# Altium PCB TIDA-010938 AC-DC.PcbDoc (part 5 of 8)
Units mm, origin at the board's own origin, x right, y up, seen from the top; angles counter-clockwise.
Board outline 280 x 180.15 mm, 4 copper layers (Top Layer, Layer 1, Layer 2, Bottom Layer), stack 1.787 mm thick; 723 components, 427 nets, 2244 pads, 2295 vias.
Unrouted connection lines stored in the file: 17.
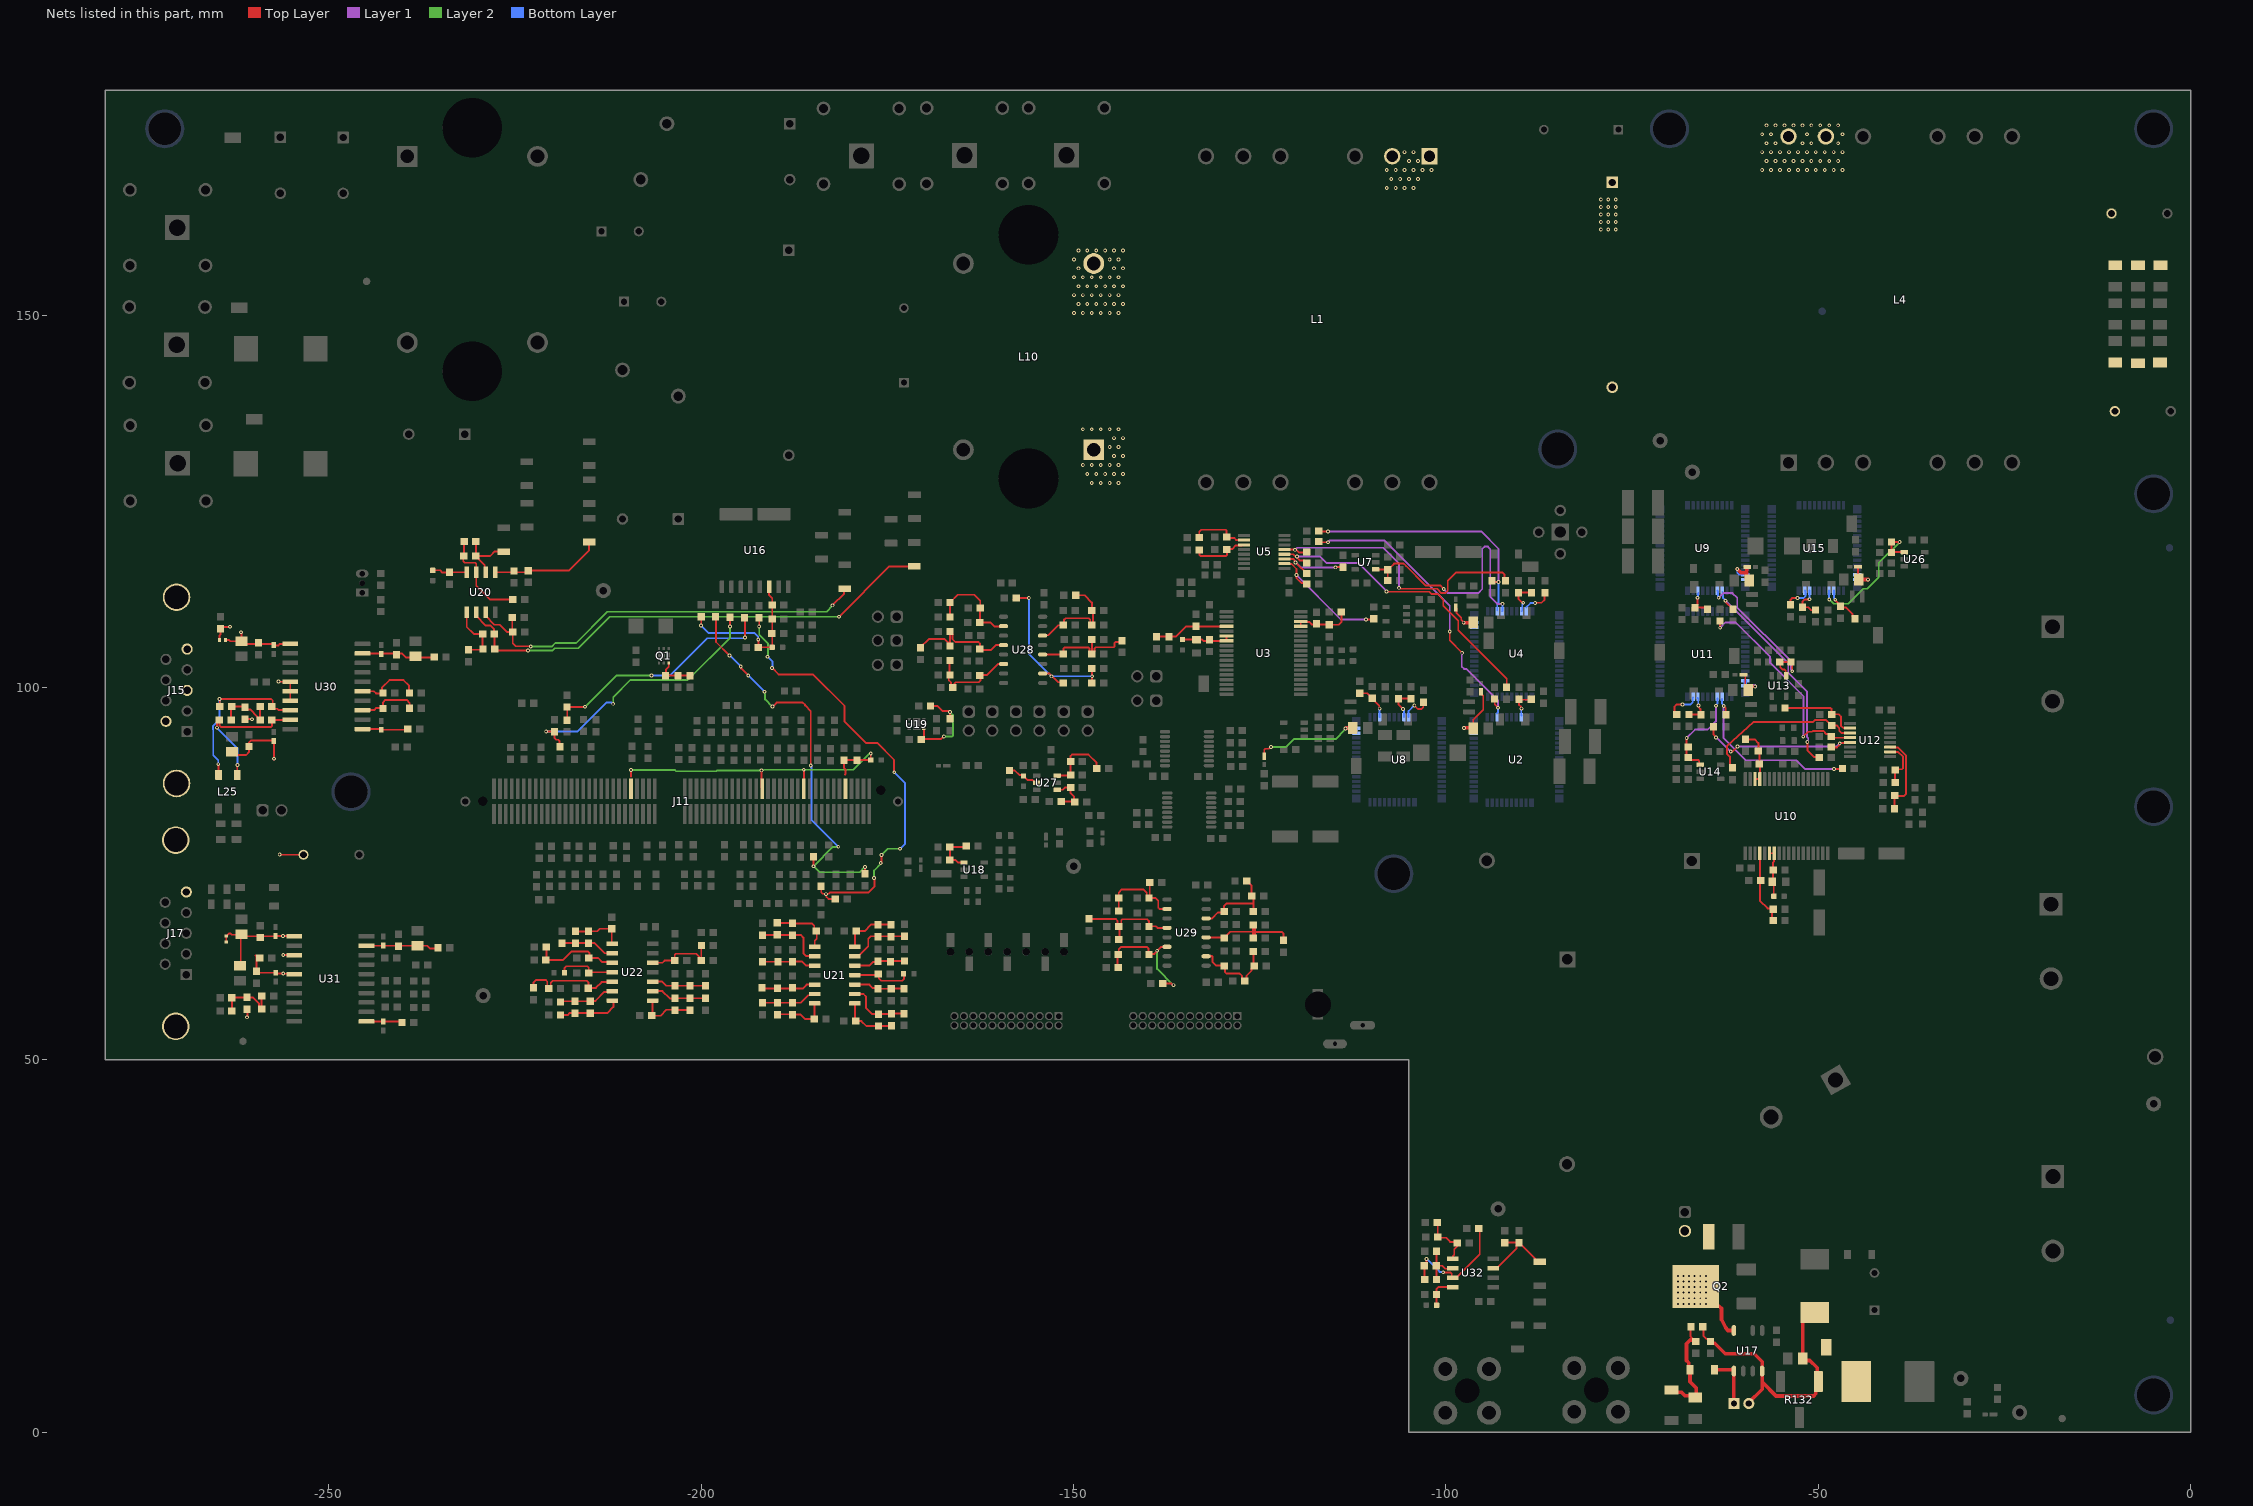
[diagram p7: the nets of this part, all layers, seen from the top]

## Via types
v1: diameter 0.508, hole 0.254, Top Layer to Bottom Layer, tented both sides, 2041 vias
v2: diameter 0.508, hole 0.254, Top Layer to Bottom Layer, 252 vias
v3: diameter 0.5, hole 0.2, Top Layer to Bottom Layer, 2 vias

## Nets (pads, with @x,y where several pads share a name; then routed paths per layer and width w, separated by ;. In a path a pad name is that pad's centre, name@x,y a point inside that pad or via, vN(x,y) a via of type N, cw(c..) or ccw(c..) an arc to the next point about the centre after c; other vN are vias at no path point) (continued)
F\A\U\L\T\_S3: C249.2 R331.2 U9.46 U13.1 | length 22
  Top Layer w0.25: C249.2@-55.19,103.421 R331.2@-53.69,103.421 -53.515,103.246 v1(-53.515,102.171) ; C249.2@-55.19,103.449 -55.121,103.38 -55.121,102.692 -54.85,102.421 -54.59,102.421 -54.39,102.221 -54.39,101.821 U13.1@-54.462,101.893
  Layer 1 w0.25: v1(-63.39,112.046) -62.765,112.671 -61.54,112.671 -60.89,112.021 -60.89,110.721 -53.658,103.489 -53.658,102.411 -53.499,102.251 v1@-53.421,102.251
  Bottom Layer w0.25: U9.46@-63.575,112.996 -63.475,112.896 -63.475,112.175 -63.39,112.09 v1@-63.39,112.021
F\A\U\L\T\_S4_init: C254.2 R336.2 U15.46 U26.1 | length 19.6
  Top Layer w0.25: C254.2@-40.19,118.121 -40.14,118.171 U26.1@-38.465,118.171 -38.34,118.171 U26.1@-38.315,118.196 ; C254.2@-40.14,118.371 -40.19,118.421 R336.2@-40.19,119.521 -39.313,119.521 -39.163,119.371 v1@-39.115,119.371
  Layer 2 w0.25: v1(-48.54,111.821) -47.961,111.242 -46.008,111.242 -44,113.25 -43.45,113.25 -41.9,114.8 -41.9,116.711 v1(-39.09,119.521)
  Bottom Layer w0.25: U15.46@-48.575,112.996 -48.558,112.978 -48.558,111.838 v1(-48.54,111.821)
F\A\U\L\T\_S5: C247.2 R329.2 U4.46 U7.1 | length 34.1
  Top Layer w0.25: U7.1@-109.45,115.85 -108.025,115.85 C247.2@-107.947,115.928 ; R329.2@-107.825,114.325 R329.2@-107.8,114.35 ; R329.2@-107.775,114.5 -107.817,114.542 C247.2@-107.817,115.798 -107.825,115.807 -107.825,115.928 -107.662,115.928 -106.965,116.625 -105.679,116.625 -105.358,116.303 -102.754,113.7 -100.8,113.7 v1(-100.3,113.2)
  Layer 1 w0.25: v1(-100.3,113.2) -99.775,112.675 -95.671,112.675 -95.127,113.219 -95.127,116.239 -95.131,116.243 -95.131,118.599 -94.821,118.909 -94.383,118.909 -94.055,118.581 -94.055,112.178 -93.102,111.225 v1(-92.4,111.225)
  Bottom Layer w0.25: U4.46@-92.465,110.225 -92.433,110.258 -92.433,111.217 v1@-92.4,111.25
F\A\U\L\T\_S6: C48.2 R33.2 U11.46 U14.1 | length 12.9
  Top Layer w0.25: C48.2@-67.69,90.621 -67.34,90.271 -66.14,90.271 -65.99,90.121 U14.1@-65.99,89.621 ; C48.2@-67.69,90.721 -67.69,91.821 v1(-67.69,93.221)
  Layer 1 w0.25: v1(-67.69,93.221) -66.553,94.358 -64.853,94.358 -63.765,95.446 v1(-63.765,97.546) v1@-63.765,97.571
  Bottom Layer w0.25: v1(-63.765,97.546) -63.765,97.615 -63.565,97.815 U11.46@-63.565,98.521
GND_ISO_COMM: C1.1 C198.1 C205.2 C207.2 C211.1 C220.1 C223.1 C224.2 C225.2 C226.1 C227.2 C228.2 C236.1 FB18.2 FB23.1 FB23.2 J15.3 J15.5 J15.6 J15.10 J15.11 J17.5 J17.10 J17.11 R126.1 U30.15 U30.16 U30.17 U31.11 U31.13 U31.15 | length 44.1
  Top Layer w0.25: FB18.2@-264.652,106.371 -264.652,106.973 -264.506,107.119 C211.1@-264.506,107.885 -264.506,108.058 -264.439,108.125 v1@-263.2,108.125 ; FB23.1@-263.75,65.85 FB23.2@-263.75,66.65 -263.7,66.65 -263.37,66.98 -263.18,66.98 -263,66.8 C228.2@-261.8,66.8 ; C207.2@-262.982,91.618 -262.982,91.601 -262.313,90.932 -261.083,90.932 -260.696,91.319 -260.696,92.073 -260.696,92.596 -260.394,92.898 -257.496,92.898 -257.359,92.761 -257.359,90.441 -257.4,90.4 v1@-257.352,90.352 ; C225.2@-261.9,62.632 -261.795,62.737 C228.2@-261.795,66.705 ; C228.2@-261.719,66.861 -261.465,66.607 C227.2@-257.311,66.607 ; C220.1@-261.247,95.749 -260.274,95.749 v1@-260.25,95.725 ; C236.1@-260.946,56.782 -260.9,56.736 v1@-260.9,55.7 ; -259.8,64 -259.7,63.9 C223.1@-259.7,61.9 C223.1@-259.7,61.727 ; C223.1@-259.3,61.7 C224.2@-257.1,61.7 -257,61.6 v1(-256.1,61.6) -256.059,61.559 -255.159,61.559 U31.15@-255.1,61.5 ; C227.2@-257.136,66.634 v1(-256.138,66.634) -255.141,66.634 U31.11@-255.075,66.7 ; v1@-256.775,100.75 -256.593,100.75 -256.581,100.762 U30.15@-255.156,100.762 U30.16@-255.156,99.492 -255.156,98.356 U30.17@-255.15,98.35 ; v1@-256.5,77.525 -256.485,77.54 C1.1@-253.416,77.54 ; v1(-256.1,64.1) -256.08,64.079 -254.64,64.079 U31.13@-254.62,64.059
  other v1: -260.974,55.717 -256.575,77.575 -257.323,90.428 -260.275,95.725 -256.725,100.8 -263.225,108.15
IAC_F\A\U\L\T\: C113.2 R88.2 R229.1 | length 54.6
  Top Layer w0.25: R88.2@-198,109.3 -198,106.1 v1(-196.2,104.3) ; v1@-194.7,102.9 -194.625,102.825 -194.625,102.567 v1(-193.674,101.617) ; v1(-190.4,97.43) -189.871,97.959 -186.356,97.959 -186.046,97.649 -186.046,97.594 -185.274,96.822 v1(-185.274,89.517) ; v1@-184.9,76.1 -184.9,77.243 R229.1@-184.892,77.251 ; v1(-178,75.9) -178,75.3 C113.2@-177.8,75.1
  Layer 2 w0.25: v1@-191.425,99.418 -191.425,99.185 -191.4,99.16 -191.4,98.4 -190.43,97.43 v1(-190.4,97.43) ; v1@-181.5,78.6 -182.3,78.6 v1(-184.9,76) -184.1,75.2 -178.7,75.2 v1(-178,75.9)
  Bottom Layer w0.25: v1(-196.2,104.3) -196.179,104.3 -194.769,102.89 -194.697,102.89 v1@-194.687,102.9 ; v1@-193.6,101.6 -193.6,101.543 v1(-191.474,99.417) ; v1@-185.2,89.5 -185.2,82.243 v1(-181.574,78.617)
  other v1: -194.674,102.817
IAC_O\C\: C108.2 R87.2 R231.1 | length 60.7
  Top Layer w0.25: v1(-192.2,108.189) R87.2@-192.2,109.2 ; v1(-190.474,102.617) -189.607,101.75 -184.984,101.75 -180.745,97.511 -180.745,95.397 -177.894,92.546 -176.351,92.546 -174.1,90.295 v1@-174.1,88.6 ; R231.1@-184.085,73.5 R231.1@-183.876,73.291 -183.876,72.476 -183.699,72.299 -183.299,72.299 v1(-183.25,72.25) ; C108.2@-182.1,71.6 -182.875,71.6 -183.201,71.926 -183.201,72.131 -183.25,72.18 v1(-183.25,72.25) ; v1@-176.7,74.545 -176.7,73.336 -177.586,72.45 -182.724,72.45 -182.875,72.299 -183.201,72.299 v1(-183.25,72.25) ; v1@-175.8,76.6 -175.774,76.626 v1(-175.774,77.517)
  Layer 2 w0.25: v1(-192.2,108.189) -192.2,107.048 -191,105.848 v1@-191,104.1 ; v1(-176.774,74.417) -176.774,75.426 v1@-175.8,76.4 ; v1@-175.8,77.5 -174.957,78.343 v1(-173.303,78.343)
  Bottom Layer w0.25: v1(-191.074,104.117) -190.4,103.443 v1@-190.4,102.6 ; v1(-174.074,88.617) -172.608,87.151 -172.608,78.992 v1@-173.2,78.4
  other v1: -175.874,76.417
IAC_REF: C112.2 R86.1 R181.1 | length 36.6
  Top Layer w0.25: v1(-220.8,94.1) -219.726,94.1 C112.2@-219.698,94.072 -219.698,93.223 -219.45,92.975 -219.171,92.975 -219.025,92.829 -219.025,92.4 -218.875,92.25 R181.1@-218.825,92.25 ; v1(-196.1,108.189) R86.1@-196.1,109.2
  Layer 2 w0.25: v1(-211.8,97.8) -211.8,98.698 -209.498,101 -201.802,101 -196.1,106.702 v1(-196.1,108.189)
  Bottom Layer w0.25: v1(-220.8,94.1) -216.565,94.1 -212.665,98 -212.07,98 -211.87,97.8 v1(-211.8,97.8)
IAC_sense: C107.2 R83.2 R180.1 | length 32
  Top Layer w0.25: R180.1@-218.1,95.7 -217.975,95.825 C107.2@-217.975,97.375 -217.95,97.4 v1@-215.5,97.4 ; v1(-194.1,106.7) R83.2@-194.1,109.2
  Layer 2 w0.25: v1(-215.574,97.417) -211.391,101.6 v1@-206.6,101.6
  Bottom Layer w0.25: v1(-206.674,101.617) -204.133,101.617 -199.15,106.6 v1@-194.2,106.6
IN_PWM_S1: C13.2 R9.2 U2.45 | length 40.1
  Top Layer w0.25: R9.2@-117.075,119.6 -116.975,119.5 -115.95,119.5 v1@-115.875,119.575 ; v1(-99.5,107.525) -99.5,106.325 v1@-97.85,104.675 ; C13.2@-93.475,98.403 -93.446,98.375 -93.446,97.721 v1(-93,97.275)
  Layer 1 w0.25: v1(-115.85,119.5) -115.825,119.5 -115.575,119.75 -108.275,119.75 -99.5,110.975 v1(-99.5,107.525) ; v1@-97.781,104.575 -97.83,104.575 -97.874,104.531 -97.874,104.418 -97.879,104.414 -97.879,102.806 -97.569,102.496 -97.287,102.496 -93,98.209 v1(-93,97.275)
  Bottom Layer w0.25: U2.45@-93.175,96.5 -93.029,96.646 -93.029,97.246 v1(-93,97.275)
  other v1: -97.825,104.65
IN_PWM_S3: C59.2 R19.2 U9.45 | length 29.6
  Top Layer w0.25: v1(-62.463,111.642) -62.414,111.592 -62.414,111.469 -61.49,110.546 C59.2@-61.49,110.521 ; v1(-51.49,92.696) -51.49,91.546 -50.619,90.674 -49.969,90.674 R19.2@-49.89,90.596
  Layer 1 w0.25: v1(-62.463,111.642) -54.058,103.237 -54.058,101.966 -51.519,99.426 -51.519,93.961 -51.511,93.953 -51.511,93.318 -51.371,93.178 -51.371,92.885 -51.49,92.765 v1(-51.49,92.696)
  Bottom Layer w0.25: U9.45@-62.89,112.821 -62.825,112.756 -62.825,112.073 -62.463,111.711 v1(-62.463,111.642)
IN_PWM_S5: C26.1 R8.2 U4.45 | length 34.3
  Top Layer w0.25: R8.2@-117.075,121 -117.025,120.95 v1@-115.95,120.95 ; C26.1@-93.8,114.3 -93.648,114.148 v1(-92.96,114.148)
  Layer 1 w0.25: v1(-115.85,120.95) -95.292,120.95 -92.95,118.608 -92.95,114.158 v1(-92.96,114.148)
  Bottom Layer w0.25: U4.45@-93.115,110.325 -93.115,111.26 -92.96,111.415 v1(-92.96,114.148)
IN_PWM_S6: C71.2 R18.2 U11.45 | length 24.1
  Top Layer w0.25: v1(-62.715,97.521) -62.715,97.471 -62.44,97.196 -62.44,96.421 C71.2@-62.39,96.371 ; v1(-47.915,89.071) -47.09,89.071 R18.2@-47.065,89.046
  Layer 1 w0.25: v1@-62.715,97.496 -62.765,97.446 -62.765,93.222 -59.763,90.221 -52.963,90.221 -51.813,89.071 v1(-47.915,89.071)
  Bottom Layer w0.25: U11.45@-62.94,98.471 -62.94,97.815 -62.715,97.59 v1(-62.715,97.521)
NetC6_1: C6.1 R23.1 R113.2 U20.3 | length 56.7
  Top Layer w0.25: U20.3@-228.915,110.075 -228.915,109.6 -227.74,108.425 -227.032,108.425 -226.031,107.424 -225.434,107.424 R23.1@-225.358,107.5 ; C6.1@-225.358,109.366 R23.1@-225.358,107.5 ; v1(-222.871,105.49) -222.92,105.539 -224.89,105.539 -225.281,105.931 R23.1@-225.281,107.424 R23.1@-225.358,107.5 ; v1(-182.368,111.023) -180.811,112.58 -180.811,113.166 R113.2@-180.717,113.259
  Layer 2 w0.25: v1(-222.871,105.49) -220.03,105.49 -219.551,105.97 -216.78,105.97 -212.585,110.165 -183.15,110.165 v1@-182.368,110.947
NetC7_2: C7.2 R2.1 R3.2 U21.3 | length 6.8
  Top Layer w0.25: U21.3@-179.347,60.117 -177.396,60.117 -176.929,59.65 -176.3,59.65 -176.2,59.55 R2.1@-174.475,59.55 ; R2.1@-174.475,59.575 -172.8,59.575 R3.2@-172.775,59.55
NetC8_1: C8.1 R4.2 R97.2 U21.2 | length 8.6
  Top Layer w0.25: U21.2@-179.347,58.847 -178.198,58.847 -177.885,58.534 -177.885,57.031 -177.004,56.15 C8.1@-176.2,56.15 -176.175,56.175 R97.2@-174.45,56.175 -174.4,56.225 R4.2@-172.75,56.225
NetC8_2: C8.2 R97.1 R140.1 U21.1 | length 7.8
  Top Layer w0.25: U21.1@-179.347,57.577 -179.347,55.57 -179.137,55.279 R140.1@-179.008,55.101 ; R140.1@-179.219,55.22 -179.008,55.22 -178.469,55.22 -177.799,54.55 C8.2@-176.2,54.55 ; C8.2@-176.25,54.325 -176.225,54.325 C8.2@-176.075,54.175 ; C8.2@-176.175,54.575 R97.1@-174.45,54.575
NetC9_2: C9.2 R119.1 R137.2 U21.5 | length 6.9
  Top Layer w0.25: U21.5@-179.347,62.657 -177.42,62.657 -176.916,63.161 -176.289,63.161 C9.2@-176.225,63.225 -176.175,63.275 R137.2@-172.7,63.275
NetC14_2: C14.2 R10.2 U2.50 | length 3.8
  Top Layer w0.25: v1@-89.9,97.275 -89.9,97.4 -90.2,97.7 R10.2@-90.2,98.425 -90.125,98.35 C14.2@-88.675,98.35
  Bottom Layer w0.25: v1(-89.875,97.15) -89.888,97.137 -89.888,96.288 U2.50@-89.85,96.25
NetC15_1: C15.1 D4.1 U2.40 U2.41 | length 8.6
  Top Layer w0.25: C15.1@-96.341,94.5 -96.341,95.659 -95,97 -95,98.884 -95.146,99.03 -95.175,99.03 -95.3,99.155 D4.1@-95.3,99.43
  Top Layer w0.5: v1(-97.575,94.575) -96.675,94.575 C15.1@-96.6,94.5
  Bottom Layer w0.25: v1(-97.575,94.575) -97.537,94.537 -96.298,94.537 U2.41@-96.26,94.5 U2.40@-96.26,93.85
NetC18_2: C18.2 C22.1 FB2.2 U3.6 U3.7 | length 6.7
  Top Layer w0.25: FB2.2@-135.475,106.425 FB2.2@-135.375,106.425 C18.2@-133.475,106.425 -132.737,106.425 -132.562,106.25 U3.7@-129.45,106.25 ; U3.7@-129.45,106.325 U3.6@-129.45,106.9
NetC21_1: C21.1 R12.2 R15.1 U3.33 U3.34 | length 7.6
  Top Layer w0.25: U3.33@-119.5,108.25 U3.34@-119.5,108.85 -119.45,108.8 -118.375,108.8 -118.05,108.475 R12.2@-115.675,108.475 ; R12.2@-115.675,108.425 -114.4,108.425 -114.05,108.775 R15.1@-114.05,109.975
NetC23_2: C23.2 R13.2 R14.2 U3.4 | length 10
  Top Layer w0.25: R14.2@-138.875,106.825 R13.2@-137.2,106.825 ; R13.2@-137.175,106.825 -136.25,106.825 -134.875,108.2 C23.2@-133.55,108.2 -131.9,108.2 ; -131.975,108.2 U3.4@-129.45,108.2
NetC25_2: C25.2 U4.51 | length 3.7
  Top Layer w0.25: v1@-87.9,111.375 -87.175,111.375 -86.75,111.8 -86.75,112.675 C25.2@-86.7,112.725
  Bottom Layer w0.25: U4.51@-89.225,110.75 -88.654,111.321 -88.054,111.321 v1(-88.025,111.35)
NetC27_2: C27.2 R30.2 U4.50 | length 4.5
  Top Layer w0.25: v1@-89.7,111.3 -90.25,111.85 R30.2@-90.25,112.725 -88.65,112.725 C27.2@-88.6,112.675
  Bottom Layer w0.25: U4.50@-89.865,110.225 -89.765,110.325 -89.765,111.165 -89.655,111.275 v1@-89.6,111.275
  other v1: -89.625,111.375
NetC28_1: C28.1 D10.1 U4.40 U4.41 | length 6
  Top Layer w0.25: D10.1@-98.7,110.73 -98.6,110.63 -98.6,110 -97.95,109.35 -97.95,109.095 -97.625,108.77 v1(-97.625,108.7) ; C28.1@-96.2,108.5 C28.1@-96.07,108.37
  Top Layer w0.5: v1(-97.625,108.7) C28.1@-96.316,108.7
  Bottom Layer w0.25: v1(-97.625,108.7) -97.612,108.713 -96.238,108.713 U4.41@-96.225,108.7
  Bottom Layer w0.5: U4.40@-96.225,108.075 U4.41@-96.225,108.7
NetC29_2: C29.2 R16.2 R105.2 U19.4 | length 13.3
  Top Layer w0.25: U19.4@-170.085,94.426 -170.085,93.35 -170.185,93.25 -170.2,93.25 C29.2@-170.45,93 -170.386,93.064 -167.82,93.064 -167.483,93.401 v1(-167.413,93.401) ; R16.2@-169.2,97.5 -168.25,97.5 -167.575,96.825 -166.595,96.825 -166.595,95.805 R105.2@-166.6,95.8
  Layer 2 w0.25: v1(-167.413,93.401) -166.314,93.401 -166.168,93.548 -166.168,96.245 -166.595,96.672 v1(-166.595,96.708)
NetC32_2: C32.2 R32.1 U5.2 | length 17.5
  Top Layer w0.25: U5.2@-121.675,116.613 -121.635,116.572 -120.734,116.572 -120.066,115.905 -120.066,115.1 -120.066,114.691 -119.404,114.029 -118.979,114.029 C32.2@-118.85,113.9 ; v1(-110.75,109.125) -109.7,109.125 R32.1@-109.65,109.075
  Layer 1 w0.25: v1(-120.075,115.1) -114.1,109.125 -110.825,109.125 v1@-110.8,109.1
NetC33_2: C33.2 R29.1 U5.3 | length 10.5
  Top Layer w0.25: U5.3@-121.675,117.248 -120.525,117.248 -120.238,116.961 -120.238,116.84 v1(-120.189,116.791) ; v1@-120.15,116.791 -120.15,116.75 C33.2@-118.65,115.25 ; v1@-114.75,116.05 -114.65,116.15 R29.1@-113.8,116.15
  Layer 1 w0.25: v1(-120.189,116.791) -120.135,116.791 -119.469,116.125 v1(-114.85,116.125)
NetC34_2: C34.2 R27.1 U5.4 | length 40.9
  Top Layer w0.25: U5.4@-121.675,117.883 -120.479,117.883 v1@-120.079,117.483 ; v1(-119.982,117.568) -119.994,117.568 v1@-120.079,117.483 ; C34.2@-118.9,116.625 -118.9,116.9 -119.05,117.05 -119.646,117.05 v1@-120.079,117.483 ; v1(-107.975,112.875) -107.946,112.846 -102.246,112.846 -101.95,112.55 -101.127,112.55 -100.371,111.794 -100.371,110.971 -98.35,108.95 -98.35,107.675 -91.85,101.175 R27.1@-91.85,100.025
  Layer 1 w0.25: v1(-119.982,117.568) -116.891,117.568 -116.044,116.721 -115.606,116.721 -115.602,116.725 -111.775,116.725 -107.975,112.925 v1(-107.975,112.875)
NetC35_2: C35.2 R25.1 U5.5 | length 38.8
  Top Layer w0.25: U5.5@-121.675,118.518 -120.093,118.518 -119.675,118.1 -118.85,118.1 C35.2@-118.825,118.075 ; v1(-106.3,113.375) -106.23,113.375 -106.101,113.246 -101.18,113.246 -100.605,112.671 -100.081,112.671 -99.771,112.981 -99.771,114.329 -98.65,115.45 -92.425,115.45 -92.125,115.15 -92.125,114.275 R25.1@-91.975,114.125
  Layer 1 w0.25: v1(-120.25,118.475) -119.975,118.75 -108.45,118.75 -106.3,116.6 v1(-106.3,113.375)
NetC41_2: C41.2 R22.2 U5.11 | length 7.3
  Top Layer w0.25: R22.2@-133.1,118.2 -133.1,117.8 -132.925,117.625 -129.546,117.625 -129.4,117.771 -129.4,118.525 -129.352,118.574 -128.721,118.574 -128.22,119.075 U5.11@-127.35,119.075
NetC42_2: C42.2 R20.2 U5.10 | length 7.4
  Top Layer w0.25: R20.2@-133.125,120.45 -133.125,120.875 -132.825,121.175 -129.596,121.175 -129.45,121.029 C42.2@-129.45,120.225 ; C42.2@-129.35,120.075 -128.45,120.075 -128.191,119.816 -127.154,119.816 U5.10@-127.125,119.788
NetC45_1: C45.1 R36.1 R118.2 U20.5 | length 14.9
  Top Layer w0.25: U20.5@-227.638,115.468 U20.5@-227.645,115.475 -223.422,115.475 R36.1@-223.2,115.697 -217.776,115.697 -215.033,118.44 R118.2@-215.033,119.532
NetC50_2: C50.2 U8.51 | length 4.1
  Top Layer w0.25: v1(-104.25,97.596) -103.754,97.1 -103.3,97.1 -103.05,97.35 -103.05,98.025 C50.2@-103.075,98.05
  Bottom Layer w0.25: U8.51@-105.008,96.025 -105.008,96.838 v1(-104.25,97.596)
NetC51_2: C51.2 R35.2 U8.45 | length 5
  Top Layer w0.25: R35.2@-111.525,99.175 R35.2@-111.575,99.225 -110.575,99.225 -109.9,98.55 C51.2@-109.9,98.525 -109.9,98.5 -108.949,97.549 -108.949,97.199 v1(-108.9,97.15)
  Bottom Layer w0.25: U8.45@-108.908,96.025 -108.904,96.029 -108.904,97.146 v1(-108.9,97.15)
NetC53_2: C53.2 R40.2 U8.50 | length 4.4
  Top Layer w0.25: v1@-105.8,97.125 -106.35,97.675 -106.35,98.45 R40.2@-106.4,98.5 C53.2@-104.7,98.5
  Bottom Layer w0.25: v1(-105.775,97.1) -105.775,97.03 -105.658,96.913 U8.50@-105.658,96.025
NetC54_1: C54.1 D25.1 U8.40 U8.41 | length 16.3
  Top Layer w0.25: D25.1@-124.4,90.77 -124.4,91.646 -124.275,91.771 -123.799,91.771 -123.57,92 v1(-123.5,92)
  Top Layer w0.5: v1@-113.425,94.525 -113.4,94.55 C54.1@-112.541,94.55 C54.1@-112.241,94.55
  Layer 2 w0.25: v1(-123.5,92) -121.5,92 -120.429,93.071 -114.829,93.071 -113.604,94.296 -113.604,94.301 -113.443,94.463 -113.437,94.463 v1@-113.437,94.468
  Bottom Layer w0.25: v1(-113.475,94.5) -113.463,94.513 -112.031,94.513 -112.018,94.5 U8.40@-112.018,93.875
NetC55_2: C55.2 FB11.2 U27.5 | length 4.3
  Top Layer w0.25: C55.2@-158.6,88.85 -157.883,88.85 -157.293,88.259 -156.859,88.259 -156.2,87.6 -155.525,87.6 -155.15,87.225 U27.5@-154.95,87.225
NetC56_2: C56.2 R68.1 R110.2 U32.3 | length 10.9
  Top Layer w0.25: U32.3@-93.675,22.035 -93.2,22.035 -90.521,24.714 -90.521,25.131 R68.1@-90.181,25.471 ; C56.2@-92.114,25.471 R68.1@-90.181,25.471 ; R68.1@-90.171,25.456 -87.9,23.186 R110.2@-87.9,22.576 ; R68.1@-90.171,25.481 R68.1@-90.181,25.471
NetC60_2: C60.2 R44.2 U9.50 | length 4.3
  Top Layer w0.25: C60.2@-66.69,110.921 -66.415,110.921 -66.24,111.096 v1@-66.24,111.921 ; v1@-66.315,111.971 v1@-66.253,111.908 ; C60.2@-66.29,110.421 C60.2@-66.59,110.721 -65.19,110.721 R44.2@-64.99,110.521
  Bottom Layer w0.25: v1@-66.16,112.021 -66.168,112.028 -66.168,112.643 U9.50@-66.09,112.721
  other v1: -66.24,112.046
NetC61_1: C61.1 D26.1 U9.40 U9.41 | length 5.9
  Top Layer w0.5: v1(-60.9,115.9) -60.898,115.9 -60.544,115.546 -60.531,115.546 -60.385,115.4 -59.668,115.4 -59.668,114.714 C61.1@-59.299,114.346 ; C61.1@-59.63,114.841 -59.63,115.4 -59.63,116.121 D26.1@-59.59,116.121
  Bottom Layer w0.25: v1(-60.9,115.9) -60.898,115.898 -60.898,115.398 -60.671,115.171 U9.40@-60.171,115.171 ; U9.40@-59.815,115.146 -59.79,115.146 -59.765,115.121 -59.765,114.98 U9.41@-59.765,114.596
NetC64_2: C64.2 C67.1 FB4.2 U10.6 U10.7 | length 6.6
  Top Layer w0.25: U10.6@-56.565,77.746 -56.015,77.746 U10.7@-55.965,77.696 ; C64.2@-56.215,73.921 -56.153,73.858 -55.99,73.696 FB4.2@-55.99,71.971 ; C64.2@-56.09,73.921 -56.09,76.496 -55.965,76.621 U10.7@-55.965,77.696 ; U10.7@-55.915,77.746 U10.7@-55.965,77.696
NetC66_1: C66.1 R45.2 R49.1 U10.33 U10.34 | length 7.2
  Top Layer w0.25: R49.1@-59.79,93.021 -58.565,93.021 -58.065,92.521 R45.2@-58.065,91.621 ; U10.34@-58.515,87.696 U10.33@-57.965,87.696 ; R45.2@-58.09,91.396 -57.915,91.221 C66.1@-57.915,89.721 ; U10.33@-57.865,87.696 C66.1@-57.865,89.721
NetC68_2: C68.2 R46.2 R48.2 U10.4 | length 10.1
  Top Layer w0.25: U10.4@-57.865,77.746 -57.865,74.071 -57.865,71.396 -56.819,70.349 -56.345,70.349 R46.2@-56.215,70.22 ; R48.2@-56.215,68.671 -56.215,70.096 R46.2@-56.115,70.196
NetC70_2: C70.2 U11.51 | length 4.4
  Top Layer w0.25: C70.2@-69.315,96.371 -69.315,97.446 -69.04,97.721 -68.34,97.721 v1@-68.29,97.771
  Bottom Layer w0.25: v1(-68.265,97.721) -67.165,97.721 -66.865,98.021 -66.865,98.621 U11.51@-66.84,98.646
NetC72_2: C72.2 R60.2 U11.50 | length 4.1
  Top Layer w0.25: C72.2@-67.565,96.371 R60.2@-65.84,96.371 ; v1(-66.09,97.596) -66.065,97.571 -66.065,97.321 -65.84,97.096 R60.2@-65.84,96.396
  Bottom Layer w0.25: U11.50@-66.215,98.596 -66.133,98.513 -66.133,97.638 v1(-66.09,97.596)
NetC73_1: C73.1 D27.1 U11.40 U11.41 | length 4.1
  Top Layer w0.25: D27.1@-59.82,101.721 -59.82,100.451 C73.1@-59.79,100.421
  Top Layer w0.5: C73.1@-59.649,100.146 v1(-58.49,100.146)
  Bottom Layer w0.5: U11.41@-59.815,100.321 U11.40@-59.815,100.896 ; U11.41@-59.49,100.221 -58.567,100.221 -58.492,100.146 v1(-58.49,100.146)
NetC74_1: C74.1 R129.2 R130.2 U20.6 | length 8.7
  Top Layer w0.25: R130.2@-230.222,119.58 -230.222,117.69 C74.1@-230.273,117.64 ; U20.6@-228.915,115.475 -229.035,115.595 -229.035,116.431 -229.894,117.29 -229.923,117.29 C74.1@-230.273,117.64 ; R129.2@-226.513,118.237 -226.538,118.262 -227.713,118.262 -228.336,117.64 C74.1@-230.273,117.64
NetC74_2: C74.2 R120.1 R130.1 U20.7 | length 13.2
  Top Layer w0.25: R130.1@-231.822,119.58 -231.822,117.69 C74.2@-231.873,117.64 -231.936,117.576 -231.936,116.947 -231.727,116.738 -230.331,116.738 -230.185,116.592 U20.7@-230.185,115.475 -230.185,113.679 -228.291,111.785 R120.1@-225.269,111.785
NetC75_1: C75.1 R124.2 R131.2 U20.2 | length 67.4
  Top Layer w0.25: U20.2@-230.185,110.075 -230.185,109.6 -228.891,108.306 -228.231,108.306 -227.814,107.889 -227.814,107.26 R131.2@-227.739,107.185 -227.739,105.217 -227.474,104.951 v1(-223.248,104.951) ; v1(-181.479,109.499) -174.723,116.256 R124.2@-171.386,116.256
  Layer 2 w0.25: v1(-223.248,104.951) -219.969,104.951 -219.662,105.258 -216.492,105.258 -212.25,109.5 v1(-181.479,109.499)
NetC75_2: C75.2 R121.1 R131.1 U20.1 | length 8.6
  Top Layer w0.25: U20.1@-231.455,110.075 -231.455,108.116 -230.524,107.185 R131.1@-229.339,107.185 -229.339,105.217 C75.2@-229.276,105.153 ; R121.1@-231.3,105.104 R121.1@-231.25,105.054 -229.375,105.054 C75.2@-229.276,105.153 ; C75.2@-229.251,105.153 C75.2@-229.276,105.153
NetC77_2: C77.2 R59.1 U12.5 | length 22.2
  Top Layer w0.25: R59.1@-64.09,94.721 -64.09,93.692 v1@-63.719,93.321 ; v1@-61.815,91.396 -61.54,91.396 v1(-60.865,92.071) ; C77.2@-48.165,91.946 -47.506,91.946 -47.184,92.267 -47.184,92.45 -47.085,92.549 -45.867,92.549 U12.5@-45.79,92.626
  Layer 1 w0.25: v1@-63.79,93.296 v1(-63.74,93.296) -63.69,93.296 -61.815,91.421 v1(-61.765,91.421) ; v1@-60.765,92.09 -60.746,92.071 -47.595,92.071 -47.166,92.5 v1(-47.135,92.5)
NetC78_2: C78.2 R62.1 U12.4 | length 28.8
  Top Layer w0.25: v1(-63.19,108.021) R62.1@-63.19,108.921 ; v1@-51.94,93.496 -51.386,94.05 -50.863,94.05 -50.767,94.146 -49.276,94.146 -49.115,93.985 -49.115,93.89 -48.969,93.744 -48.638,93.744 -48.14,93.246 U12.4@-46.09,93.246
  Layer 1 w0.25: v1(-63.19,108.021) -62.49,108.721 -61.09,108.721 -56.49,104.121 -56.49,103.286 -51.99,98.786 v1@-51.99,93.487
  other v1: -52.04,93.396
NetC79_2: C79.2 R64.1 U12.3 | length 21.1
  Top Layer w0.25: R64.1@-61.79,89.421 -61.89,89.521 -61.89,90.721 -62.294,91.125 -62.294,91.64 -62.291,91.643 -62.291,92.021 -62.289,92.122 -62.213,92.198 -58.735,95.346 -50.754,95.346 -50.454,95.646 -49.226,95.646 -49.015,95.646 -48.265,94.896 C79.2@-48.24,94.896 -47.565,94.896 -47.209,94.539 -47.209,94.189 -46.915,93.896 ; -46.897,93.899 -46.444,93.899 U12.3@-46.415,93.871
NetC80_2: C80.2 R66.1 U12.2 | length 10.4
  Top Layer w0.25: R66.1@-54.49,97.221 -48.34,97.221 -48.241,97.121 -48.241,96.421 -48.215,96.396 -47.265,96.396 -46.973,96.103 -46.973,94.878 -46.629,94.534 U12.2@-46.351,94.534
NetC81_1: C81.1 R133.2 R135.1 U32.5 | length 7.7
  Top Layer w0.25: R135.1@-101.19,28.194 -101.114,28.118 R133.2@-101.114,26.251 -100.982,26.119 -99.989,26.119 -99.446,25.577 -98.702,25.577 -98.702,25.223 C81.1@-98.463,24.984 ; U32.5@-99.075,23.305 -99.075,23.658 -98.883,23.849 -98.883,24.563 C81.1@-98.463,24.984 ; C81.1@-98.463,25.438 C81.1@-98.463,24.984
NetC86_2: C86.2 R56.2 U12.11 | length 11.2
  Top Layer w0.25: U12.11@-40.34,91.991 -40.312,91.962 -39.366,91.962 -38.24,90.836 -38.24,85.746 -38.565,85.421 -39.615,85.421 C86.2@-39.765,85.271 ; R56.2@-39.79,83.721 -39.79,85.521 C86.2@-39.765,85.546
NetC87_2: C87.2 R54.2 U12.10 | length 6.5
  Top Layer w0.25: U12.10@-40.34,91.356 -39.325,91.356 -38.64,90.671 -38.64,89.167 -38.787,89.021 C87.2@-39.765,89.021 ; R54.2@-39.74,87.071 -39.74,88.871 C87.2@-39.69,88.921
NetC93_2: C93.2 R38.2 R252.2 U27.1 | length 5.9
  Top Layer w0.25: U27.1@-152.2,86.275 -151.425,86.275 -151.15,86.55 R252.2@-150.4,86.55 -150.4,85.827 -149.914,85.341 -149.914,84.714 -149.89,84.69 C93.2@-151.66,84.69 C93.2@-151.748,84.69 ; R252.2@-150.454,86.817 R252.2@-150.429,86.792
NetC95_2: C95.2 U15.51 | length 4
  Top Layer w0.152: v1@-52.883,111.928 v1(-52.815,111.996)
  Top Layer w0.25: C95.2@-53.765,110.796 -53.74,110.821 -53.74,111.796 -53.54,111.996 -52.865,111.996 v1@-52.84,112.021
  Bottom Layer w0.25: v1(-52.815,111.996) -52.004,111.996 -51.75,112.25 -51.75,112.92 U15.51@-51.825,112.996
NetC96_2: C96.2 R69.2 U15.45 | length 5.4
  Top Layer w0.25: v1(-47.74,111.771) -47.74,111.701 -47.164,111.124 -47.164,110.771 -47.139,110.746 C96.2@-47.09,110.746 ; C96.2@-47.015,110.896 -46.84,110.721 -46.29,110.721 -45.443,109.873 -45.443,109.571 -45.093,109.221 R69.2@-45.09,109.221
  Bottom Layer w0.25: U15.45@-47.925,112.996 -47.925,112.025 -47.74,111.84 v1(-47.74,111.771)
NetC97_2: C97.2 R74.2 U15.50 | length 4.9
  Top Layer w0.152: R74.2@-50.814,110.146 -50.79,110.169 R74.2@-50.79,110.196
  Top Layer w0.25: v1@-51.24,111.871 -51.294,111.817 -51.844,111.817 -52.115,111.546 C97.2@-52.115,110.771 -51.39,110.771 -50.99,110.371 -50.44,110.371 R74.2@-50.415,110.346
  Bottom Layer w0.25: v1(-51.215,111.846) -51.195,111.866 -51.195,112.976 U15.50@-51.175,112.996
NetC99_1: C99.1 D28.1 U15.40 U15.41 | length 4.8
  Top Layer w0.25: C99.1@-44.69,114.821 D28.1@-44.69,116.221
  Top Layer w0.5: C99.1@-44.574,114.496 v1@-43.315,114.496
  Bottom Layer w0.25: U15.41@-44.815,114.496 U15.40@-44.815,115.146 ; U15.41@-44.79,114.471 -44.344,114.471 v1(-43.34,114.471)
NetC100_1: C100.1 R238.1 R239.1 U32.6 | length 6.2
  Top Layer w0.25: C100.1@-101.276,20.51 -101.276,22.354 R239.1@-101.291,22.37 ; R238.1@-101.271,24.311 -101.271,22.39 R239.1@-101.291,22.37 ; U32.6@-99.075,22.035 -99.139,21.971 -100.123,21.971 -100.522,22.37 R239.1@-101.291,22.37
NetC100_2: C100.2 R134.1 R239.2 U32.7 | length 16.1
  Top Layer w0.25: C100.2@-102.876,20.51 -102.876,22.354 -102.613,22.618 v1(-102.613,23.289) ; v1@-100.302,21.448 -99.371,21.448 -99.225,21.302 -99.225,20.915 U32.7@-99.075,20.765 -98.6,20.765 -95.475,23.89 -95.475,27.226 R134.1@-95.63,27.381
  Bottom Layer w0.25: v1(-102.613,23.289) -100.862,21.539 -100.427,21.539 v1(-100.378,21.49)
NetC101_2: C101.2 R72.2 R256.2 U27.3 | length 9.3
  Top Layer w0.25: U27.3@-152.2,88.175 -150.475,88.175 R256.2@-150.4,88.25 -150.425,88.275 -150.425,90.775 -150.2,91 -148,91 -146.9,89.9 R72.2@-146.9,89.1 R72.2@-146.837,89.163
NetC103_1: C103.1 C244.1 L4.11 L4.12 L10.AI R291.1 R326.1 R327.1
  other v1: -79.215,161.492 -78.215,161.492 -77.215,161.492 -79.215,162.492 -78.215,162.492 -77.215,162.492 -79.215,163.492 -78.215,163.492 -77.215,163.492 -79.215,164.492 -78.215,164.492 -77.215,164.492 -79.215,165.492 -78.215,165.492 -77.215,165.492
  other v2: -147.552,127.464 -146.352,127.464 -145.152,127.464 -143.952,127.464 -148.152,128.664 -146.952,128.664 -145.752,128.664 -144.552,128.664 -143.352,128.664 -148.752,129.864 -147.552,129.864 -146.352,129.864 -145.152,129.864 -143.952,129.864 -144.552,131.064 -143.352,131.064 -145.152,132.264 -143.952,132.264 -144.552,133.464 -143.352,133.464 -148.752,134.664 -147.552,134.664 -146.352,134.664 -145.152,134.664 -143.952,134.664 -57.552,169.464 -56.352,169.464 -55.152,169.464 -53.952,169.464 -52.752,169.464 -51.552,169.464 -50.352,169.464 -49.152,169.464 -47.952,169.464 -46.752,169.464 -56.952,170.664 -55.752,170.664 -54.552,170.664 -53.352,170.664 -52.152,170.664 -50.952,170.664 -49.752,170.664 -48.552,170.664 -47.352,170.664 -57.552,171.864 -56.352,171.864 -55.152,171.864 -53.952,171.864 -52.752,171.864 -51.552,171.864 -50.352,171.864 -49.152,171.864 -47.952,171.864 -46.752,171.864 -56.952,173.064 -55.752,173.064 -52.152,173.064 -50.952,173.064 -47.352,173.064 -57.552,174.264 -56.352,174.264 -51.552,174.264 -46.752,174.264 -56.952,175.464 -55.752,175.464 -54.552,175.464 -53.352,175.464 -52.152,175.464 -50.952,175.464 -49.752,175.464 -48.552,175.464 -47.352,175.464
NetC103_2: C103.2 C243.2 L1.1 L1.2 L10.AII R77.2 R79.2 R80.2
  other v2: -149.952,150.264 -148.752,150.264 -147.552,150.264 -146.352,150.264 -145.152,150.264 -143.952,150.264 -149.352,151.464 -148.152,151.464 -146.952,151.464 -145.752,151.464 -144.552,151.464 -143.352,151.464 -149.952,152.664 -148.752,152.664 -147.552,152.664 -146.352,152.664 -145.152,152.664 -143.952,152.664 -149.352,153.864 -148.152,153.864 -146.952,153.864 -145.752,153.864 -144.552,153.864 -143.352,153.864 -149.952,155.064 -148.752,155.064 -147.552,155.064 -146.352,155.064 -145.152,155.064 -143.952,155.064 -149.352,156.264 -144.552,156.264 -143.352,156.264 -149.952,157.464 -145.152,157.464 -143.952,157.464 -149.352,158.664 -148.152,158.664 -146.952,158.664 -145.752,158.664 -144.552,158.664 -143.352,158.664 -107.952,167.064 -106.752,167.064 -105.552,167.064 -104.352,167.064 -107.352,168.264 -106.152,168.264 -104.952,168.264 -103.752,168.264 -107.952,169.464 -106.752,169.464 -105.552,169.464 -104.352,169.464 -103.152,169.464 -101.952,169.464 -104.952,170.664 -103.752,170.664 -105.552,171.864 -104.352,171.864
NetC109_1: C109.1 C110.1 C111.1 FB6.2 R84.1 R85.1 U16.8 | length 21
  Top Layer w0.25: v1(-200,108.31) -199.978,108.332 R84.1@-199.978,109.479 ; v1@-192.3,106.4 -192.308,106.392 R85.1@-192.308,105.34 -192.248,105.4 -190.675,105.4 -190.6,105.325 FB6.2@-190.6,105.25 ; U16.8@-190.845,113.516 -190.875,113.486 -190.875,112.4 -190.45,111.975 -190.45,105.45 FB6.2@-190.525,105.375
  Bottom Layer w0.25: v1(-200,108.31) -198.99,107.3 -192.8,107.3 -192.325,106.825 v1@-192.325,106.575
  other v1: -192.325,106.425
NetC114_1: C114.1 Q1.3 R89.2 R90.1 | length 5.1
  Top Layer w0.25: C114.1@-204.75,101.6 R90.1@-203.125,101.6 R89.2@-201.5,101.6 R89.2@-201.4,101.6 ; C114.1@-204.75,101.675 -204.725,101.7 -204.725,102.375 -204.35,102.75 Q1.3@-204.35,103.275
NetC116_1: C116.1 D14.1 U17.1 | length 6.4
  Top Layer w0.5: D14.1@-63.87,8.399 -61.407,8.399 U17.1@-61.36,8.353 ; C116.1@-61.36,4.354 U17.1@-61.36,8.226
NetC116_2: C116.2 C117.2 D20.1 L13.1 R95.1 R98.2 R132.1 TP23.1 U17.4 | length 36.4
  Top Layer w0.25: C117.2@-65.432,13.882 -65.432,12.96 R95.1@-64.471,11.999
  Top Layer w0.5: R95.1@-64.571,11.999 -64.521,11.949 -63.918,11.949 -62.518,10.549 -58.621,10.549 -57.55,9.478 U17.4@-57.55,8.226 -57.55,6.746 ; C116.2@-59.344,3.864 -59.344,4 -57.55,5.794 -57.55,6.746 ; R98.2@-52.105,9.924 -52.105,14.959 -51.233,15.831 D20.1@-50.471,15.831 ; R98.2@-51.671,9.649 -51.153,9.649 -50.172,8.668 -50.172,7.961 -50.063,7.961 R132.1@-49.983,7.881 ; R132.1@-50.013,6.816 -50.358,6.471 -50.358,5.17 -50.65,4.877 -55.681,4.877 -57.55,6.746
NetC117_1: C117.1 D14.2 D15.1 R93.2 R94.1 | length 14.9
  Top Layer w0.25: C117.1@-67.182,13.897 -67.182,12.91 -66.846,12.574 -66.821,12.574 -66.471,12.224 R93.2@-66.471,12.199 ; R93.2@-66.471,12.399 R93.2@-66.446,12.399
  Top Layer w0.5: D15.1@-69.698,5.672 -69.398,5.373 -68.371,5.373 -67.912,4.914 -66.762,4.914 R94.1@-66.53,4.682 -66.396,4.817 -66.396,5.944 -67.246,6.794 D14.2@-67.246,8.399 -67.423,8.576 -67.423,9.351 -67.721,9.649 -67.721,11.899 -67.221,12.399 R93.2@-66.471,12.399
NetC127_2: C127.2 R104.2 R107.2 U18.1 | length 5.6
  Top Layer w0.25: U18.1@-165,76.525 -165.525,76.525 -165.819,76.819 C127.2@-166.597,76.819 R107.2@-166.597,78.597 -164.578,78.597 R104.2@-164.55,78.625
NetC128_2: C128.2 FB12.2 U32.8 | length 4.5
  Top Layer w0.25: C128.2@-101.291,18.532 -101.291,19.232 -101.028,19.495 U32.8@-99.075,19.495 ; C128.2@-101.271,18.532 -101.271,17.088 FB12.2@-101.252,17.069
NetC141_2: C141.2 FB7.2 U21.4 | length 7.8
  Top Layer w0.25: U21.4@-179.347,61.387 -176.463,61.387 C141.2@-176.45,61.4 ; C141.2@-176.195,61.512 -176.15,61.467 -176.15,60.946 -175.829,60.625 -173.025,60.625 -172.75,60.9 -172.75,61.5 FB7.2@-172.725,61.525
NetC142_2: C142.2 FB8.2 U22.4 | length 7.6
  Top Layer w0.25: FB8.2@-218.244,61.65 -218.35,61.756 -218.35,62.3 -218.075,62.575 -215.25,62.575 -215.075,62.4 C142.2@-215.075,61.975 ; C142.2@-215.096,61.65 -214.971,61.775 -212.2,61.775 U22.4@-212.175,61.8
NetC143_2: C143.2 R136.1 R139.2 U22.3 | length 11.3
  Top Layer w0.25: R136.1@-220.797,63.395 -218.589,63.395 -217.433,64.55 -215.175,64.55 -215,64.375 C143.2@-215,63.925 ; R139.2@-220.797,65.173 -220.775,65.151 R136.1@-220.775,63.625 ; C143.2@-215.096,63.682 -213.832,63.682 -213.275,63.125 -212.425,63.125 U22.3@-212.4,63.15
NetC144_1: C144.1 R138.2 R142.2 U21.6 | length 8.4
  Top Layer w0.25: U21.6@-179.347,63.927 -178.872,63.927 -177.55,65.249 -177.55,66.275 -177.225,66.6 R138.2@-172.7,66.6
NetC144_2: C144.2 R142.1 R150.1 U21.7 | length 7.2
  Top Layer w0.25: U21.7@-179.347,65.197 -179.347,67.123 R150.1@-179.168,67.302 -178.059,67.302 -177.198,68.162 -174.537,68.162 R142.1@-174.525,68.15
NetC148_1: C148.1 R143.2 R145.2 U22.2 | length 7
  Top Layer w0.25: R143.2@-218.657,65.676 -218.656,65.675 C148.1@-215.225,65.675 ; C148.1@-215.101,65.676 -214.276,65.676 -212.925,64.325 U22.2@-212.125,64.325
NetC148_2: C148.2 R141.1 R145.1 U22.1 | length 6.7
  Top Layer w0.25: R145.1@-216.879,67.276 -216.853,67.25 C148.2@-215.101,67.25 ; C148.2@-215.101,67.276 -213.949,67.276 -213.625,67.6 -212.25,67.6 R141.1@-212.125,67.475 ; U22.1@-212,65.775 -211.998,65.777 R141.1@-211.998,67.475
NetC150_1: C150.1 R147.2 R149.1 U22.5 | length 13.1
  Top Layer w0.25: R149.1@-222.5,59.694 -222.475,59.719 -222.475,60.425 -222.15,60.75 -220.875,60.75 -220.65,60.525 -220.65,59.975 R147.2@-220.675,59.95 ; R147.2@-220.325,59.775 -220.175,59.925 -220.175,60.375 -219.925,60.625 -215.375,60.625 -215.1,60.35 C150.1@-215.1,59.925 ; C150.1@-215.134,59.618 -215.077,59.675 -214.125,59.675 -213.35,60.45 -212.3,60.45 U22.5@-212.2,60.55
NetC154_1: C154.1 R153.1 R155.1 U22.6 | length 7.7
  Top Layer w0.25: R153.1@-219.15,57.775 -219.047,57.878 C154.1@-214.88,57.878 -214.834,57.924 -214.176,57.924 -212.975,59.125 U22.6@-211.975,59.125
NetC154_2: C154.2 R151.1 R155.2 U22.7 | length 8.2
  Top Layer w0.25: R151.1@-218.873,56.02 -217.93,56.02 -217.65,56.3 C154.2@-214.95,56.3 ; C154.2@-214.88,56.278 -212.622,56.278 -211.775,57.125 U22.7@-211.775,57.8
NetC155_2: C155.2 R156.1 R159.2 U22.10 | length 7.2
  Top Layer w0.25: U22.10@-206.504,60.505 -205.205,60.505 -204.65,59.95 R159.2@-199.525,59.95
NetC156_1: C156.1 R157.2 R158.1 U21.10 | length 7.2
  Top Layer w0.25: R158.1@-191.769,63.181 -189.737,63.181 -187.856,63.181 C156.1@-187.8,63.125 ; C156.1@-187.675,63.3 -187.575,63.2 -186.425,63.2 -185.882,62.657 U21.10@-184.747,62.657
NetC159_1: C159.1 R162.1 R164.1 U21.9 | length 9.4
  Top Layer w0.25: R162.1@-191.675,66.725 -191.625,66.775 -186.625,66.775 -186.275,66.425 -186.275,64.304 -185.898,63.927 U21.9@-184.747,63.927
NetC159_2: C159.2 R160.1 R164.2 U21.8 | length 8
  Top Layer w0.25: R164.2@-189.77,68.379 -187.996,68.379 C159.2@-187.875,68.5 ; C159.2@-187.705,68.337 -187.669,68.301 -185.101,68.301 -184.804,68.004 -184.804,67.604 R160.1@-184.5,67.3 ; U21.8@-184.747,65.197 -184.747,65.978 -184.475,66.25 R160.1@-184.475,67.3
NetC160_1: C160.1 R163.2 R165.2 U22.9 | length 7
  Top Layer w0.25: U22.9@-206.504,59.235 -205.185,59.235 -204.2,58.25 C160.1@-203.95,58.25 ; C160.1@-203.499,58.278 R165.2@-201.467,58.278 R163.2@-199.447,58.278
NetC160_2: C160.2 R161.1 R165.1 U22.8 | length 7.5
  Top Layer w0.25: R161.1@-206.626,55.933 -205.442,55.933 -204.65,56.725 C160.2@-203.425,56.725 ; R161.1@-206.504,55.996 U22.8@-206.504,57.965 ; C160.2@-203.425,56.678 -201.572,56.678 R165.1@-201.475,56.775
NetC162_1: C162.1 R167.2 R168.1 U21.12 | length 7.3
  Top Layer w0.25: R168.1@-191.85,59.625 -191.8,59.575 -186.375,59.575 -185.833,60.117 U21.12@-184.747,60.117
NetC163_2: C163.2 R166.2 R172.1 U22.12 | length 9.4
  Top Layer w0.25: U22.12@-206.504,63.045 -205.18,63.045 -204.9,63.325 -203.8,63.325 C163.2@-203.775,63.3 ; C163.2@-203.537,63.32 -203.537,64.104 -203.391,64.25 -200.65,64.25 -200.275,63.875 R172.1@-200.275,63.675 ; R172.1@-199.981,63.32 -199.981,65.314 R166.2@-199.943,65.352
NetC166_1: C166.1 R171.1 R173.1 U21.13 | length 6.9
  Top Layer w0.25: R171.1@-191.769,57.669 C166.1@-187.819,57.669 ; C166.1@-187.738,57.673 -186.602,57.673 -185.603,58.672 -185.397,58.672 -185.25,58.819 U21.13@-185.25,58.85
NetC166_2: C166.2 R169.1 R173.2 U21.14 | length 7.1
  Top Layer w0.25: R173.2@-189.737,56.069 -189.681,56.125 C166.2@-187.8,56.125 ; C166.2@-187.6,56.075 -186.625,56.075 -186.022,55.472 R169.1@-184.832,55.472 -184.792,55.513 -184.792,57.532 U21.14@-184.747,57.577
NetC181_2: C181.2 C182.1 FB9.2 J11.48 J11.84 J11.98 J11.112 | length 45.6
  Top Layer w0.25: v1(-209.4,88.925) -209.404,88.922 -209.404,88.054 -209.375,88.025 ; v1@-191.875,88.8 -191.875,86.466 J11.84@-191.807,86.398 ; v1@-186.225,88.875 -186.207,88.857 J11.98@-186.207,86.398 ; -180.675,88.3 -180.625,88.35 -180.625,89.025 -180.828,89.228 C182.1@-180.828,90.226 -180.79,90.264 -179.05,90.264 FB9.2@-177.286,90.264 ; v1(-177.225,91.152) -177.218,91.144 -177.218,90.271 FB9.2@-177.21,90.264
  Layer 2 w0.25: v1(-209.4,88.925) -203.545,88.925 -203.366,88.746 -197.981,88.746 -197.852,88.875 v1(-191.875,88.875) -191.826,88.924 -191.643,88.924 -191.618,88.95 v1(-186.225,88.95) -179.593,88.95 -177.44,91.103 -177.274,91.103 v1(-177.225,91.152)
NetC189_2: C189.2 C191.1 C195.1 L8.2 U30.9 | length 9.8
  Top Layer w0.25: U30.9@-245.456,104.572 -240.172,104.572 -239.6,104 -236,104 L8.2@-235.9,104.1
NetC190_2: C190.2 R250.1 R263.2 R308.2 U29.2 | length 12.2
  Top Layer w0.25: R308.2@-143.975,70.15 -143.931,70.194 R263.2@-143.931,71.747 -143.931,72.469 -143.5,72.9 -140.625,72.9 -140.172,72.447 -140.172,72.047 C190.2@-140.15,72.025 ; R250.1@-139.775,73.825 -139.775,71.839 C190.2@-139.867,71.747 -139.028,71.747 -138.625,71.344 -138.625,70.45 -138.45,70.275 -137.825,70.275 U29.2@-137.8,70.25
NetC192_2: C192.2 R21.1 R260.2 R302.2 U28.2 | length 12.9
  Top Layer w0.25: R260.2@-166.7,109.45 -166.585,109.565 R302.2@-166.585,111.405 -165.54,112.45 -163.348,112.45 -162.531,111.633 R21.1@-162.531,110.668 ; R21.1@-162.729,110.579 -162.575,110.425 C192.2@-162.575,108.725 -161.175,108.725 -160.65,108.2 -159.625,108.2 U28.2@-159.575,108.15
NetC193_2: C193.2 R248.1 R267.2 R307.2 U29.4 | length 13.9
  Top Layer w0.25: R248.1@-147.9,68.925 -144.359,68.925 -144.096,68.662 -144.096,68.102 R267.2@-143.931,67.937 ; R307.2@-143.825,66.2 -143.825,67.831 R267.2@-143.931,67.937 ; C193.2@-139.867,67.937 -138.937,67.937 -138.725,67.725 -137.939,67.725 -137.889,67.675 U29.4@-137.85,67.675 ; C193.2@-139.85,68.2 -139.875,68.225 -139.875,68.625 -140.125,68.875 -143.454,68.875 -143.6,68.729 -143.6,68.268 R267.2@-143.931,67.937
NetC194_2: C194.2 R249.1 R265.2 R301.2 U28.4 | length 14.9
  Top Layer w0.25: R249.1@-170.55,105.35 -170.55,105.375 -169.425,106.5 -167.3,106.5 -166.855,106.055 -166.585,106.055 R301.2@-166.585,107.522 -166.25,107.187 -166.25,106.5 -165.85,106.1 -162.775,106.1 -162.575,105.9 C194.2@-162.575,105.575 ; C194.2@-162.575,105.169 -162.456,105.05 -161.05,105.05 -160.415,105.685 -159.585,105.685 U28.4@-159.55,105.65
NetC196_2: C196.2 R247.1 R268.2 R300.2 U28.6 | length 12.1
  Top Layer w0.25: R268.2@-166.675,101.697 R300.2@-166.675,103.55 ; R268.2@-166.585,101.697 -166.744,101.539 -166.744,100.994 -166.45,100.7 R247.1@-166.45,100.025 ; R247.1@-165.973,100.102 -165.973,100.554 -165.827,100.7 -162.7,100.7 -162.5,100.9 C196.2@-162.5,101.5 ; C196.2@-162.5,101.663 -161.662,101.663 -160.18,103.145 U28.6@-159.4,103.145
NetC197_1: C197.1 L12.2 U30.1 | length 5.9
  Top Layer w0.25: U30.1@-245.456,94.412 C197.1@-242.987,94.412 ; C197.1@-242.916,94.32 -239.555,94.32 L12.2@-239.5,94.375
NetC199_2: C199.2 R246.1 R270.2 R306.2 U29.6 | length 16.9
  Top Layer w0.25: R306.2@-144.075,62.6 -144.075,64.021 R270.2@-143.969,64.127 -143.925,64.171 -143.925,64.85 -143.6,65.175 -140.175,65.175 -139.925,64.925 C199.2@-139.925,64.375 ; C199.2@-139.867,64.127 -139.757,64.237 -139.138,64.237 -138.205,65.17 -137.555,65.17 U29.6@-137.525,65.2 ; R246.1@-138.025,60.25 -136.87,60.25 -136.654,60.034 v1(-136.584,60.034)
  Layer 2 w0.25: v1(-138.775,64.65) -138.775,62.225 v1(-136.584,60.034)
NetC200_2: C200.2 R245.1 R273.2 R299.2 U28.10 | length 24.1
  Top Layer w0.25: R245.1@-158.05,111.796 R245.1@-157.948,111.796 ; R245.1@-157.7,112 v1(-156,112) ; U28.10@-154.15,101.875 -153.25,101.875 -152.082,100.707 -151.632,100.707 C200.2@-151.575,100.65 ; R273.2@-147.543,100.602 -147.5,100.645 v1(-147.5,101.5) ; v1@-147.543,101.5 R299.2@-147.543,102.544
  Bottom Layer w0.25: v1(-156,112) -156,104.521 v1(-152.975,101.496) -152.973,101.498 -147.502,101.498 v1(-147.5,101.5)
NetC202_2: C202.2 R244.1 R274.2 R305.2 U29.10 | length 12.1
  Top Layer w0.25: U29.10@-132.2,63.915 -132.143,63.972 -131.471,63.972 -131.325,63.826 -131.325,63.125 -130.85,62.65 -130.12,62.65 -129.95,62.48 C202.2@-129.95,62.475 ; C202.2@-129.745,62.618 -129.675,62.548 -129.675,61.8 -129.45,61.575 -127.681,61.575 -127.368,61.262 -127.368,60.693 -127.15,60.475 -126.781,60.844 -126.781,61.302 -126.11,61.973 -126.11,62.253 -125.76,62.603 R274.2@-125.735,62.603 ; R305.2@-125.849,64.566 -125.849,62.953 -125.771,62.875 R274.2@-125.7,62.875
NetC204_2: C204.2 R243.1 R276.2 R298.2 U28.12 | length 15
  Top Layer w0.25: U28.12@-154.15,104.415 C204.2@-151.353,104.415 ; C204.2@-151.353,104.487 -151.353,105.229 -151.207,105.375 -148.05,105.375 -147.85,105.175 -147.85,104.7 R276.2@-147.825,104.675 ; R298.2@-147.543,106.427 R276.2@-147.543,104.485 -147.525,104.485 -147.293,104.717 -147.286,104.717 -147.168,104.835 -147.168,105.232 -147,105.4 -144.6,105.4 -144.5,105.5 -144.5,105.952 -144.352,106.1 R243.1@-143.5,106.1 ; R243.1@-143.527,106.101 R243.1@-143.405,105.978
NetC206_2: C206.2 R241.1 R281.2 R297.2 U28.14 | length 14.4
  Top Layer w0.25: U28.14@-154.15,106.955 -154.105,107 -153.425,107 -152.082,108.343 -151.38,108.343 C206.2@-151.353,108.37 -151.275,108.448 -151.275,109.1 -151.075,109.3 -147.975,109.3 -147.747,109.072 -147.747,108.572 R281.2@-147.543,108.368 -147.375,108.536 -147.375,110.142 R297.2@-147.543,110.31 -147.543,111.393 -148.525,112.375 R241.1@-149.7,112.375
NetC208_2: C208.2 R242.1 R278.2 R304.2 U29.12 | length 13.4
  Top Layer w0.25: U29.12@-132.2,66.455 -130.055,66.455 C208.2@-130,66.4 ; C208.2@-129.85,66.447 C208.2@-129.783,66.38 -129.758,66.38 -128.938,67.2 -125.775,67.2 -125.75,67.175 -122.05,67.175 -121.8,66.925 R242.1@-121.8,66.075
  Top Layer w0.5: R278.2@-125.849,66.344 -125.775,66.418 -125.775,67.2 -125.775,68.047 R304.2@-125.849,68.122
NetC209_2: C209.2 R240.1 R282.2 R303.2 U29.14 | length 12
  Top Layer w0.25: U29.14@-132.2,68.995 -131.405,68.995 -130.612,69.788 -129.987,69.788 C209.2@-129.85,69.925 ; C209.2@-129.783,69.936 -129.783,70.692 -129.5,70.975 -125.944,70.975 -125.849,70.88 ; R240.1@-126.725,74.025 -126.7,74.025 -126.35,73.675 -126.35,73.65 -126.089,73.389 R303.2@-126.089,72.001 ; R303.2@-125.989,72.001 -125.849,71.861 -125.849,70.975 -125.849,70.88 ; R282.2@-125.849,69.9 -125.849,70.88
NetC210_1: C210.1 C212.2 C213.2 FB18.1 U30.11 | length 9.9
  Top Layer w0.25: FB18.1@-263.852,106.371 -263.371,106.371 -263.2,106.2 -261.925,106.2 C213.2@-261.831,106.106 ; v1@-261.7,107.4 -261.723,107.377 C213.2@-261.723,106.215 -261.334,105.826 C210.1@-259.437,105.826 ; C210.1@-259.075,105.85 -257.25,105.85 -257,105.6 -256.975,105.625 -256.75,105.625 -256.533,105.842 U30.11@-255.156,105.842
  other v1: -261.774,107.417
NetC214_2: C214.2 C215.1 C216.1 L16.2 U31.9 | length 9.8
  Top Layer w0.25: U31.9@-244.92,65.329 -236.754,65.329 -236.375,64.95 L16.2@-235.25,64.95
NetC217_1: C217.1 C220.2 C221.2 R280.1 R287.2 | length 7.7
  Top Layer w0.25: C217.1@-263.125,95.825 -263.125,97.321 C221.2@-263.019,97.427 C220.2@-261.277,97.427 ; C220.2@-261.247,97.349 -261.247,97.324 -260.968,97.045 -260.545,97.045 -259.585,96.085 -259.585,95.995 -259.29,95.7 R280.1@-259.2,95.7 ; R287.2@-259.21,97.423 -259.21,95.995 -259.165,95.95 R280.1@-259.125,95.95
NetC217_2: C217.2 L25.1 R280.2 U30.19 | length 19.4
  Top Layer w0.25: v1@-264.964,94.602 -264.964,95.342 C217.2@-264.657,95.649 -264.657,94.932 -264.4,94.675 -262.303,94.675 -262.301,94.677 -257.802,94.677 -257.6,94.879 -257.6,95.55 R280.2@-257.55,95.6 ; v1@-262.3,89.5 -262.275,89.475 L25.1@-262.275,88.275 ; R280.2@-257.61,95.645 -257.572,95.607 -255.507,95.607 U30.19@-255.5,95.6
  Bottom Layer w0.25: v1(-265,94.6) -262.25,91.85 -262.25,89.65 v1@-262.3,89.6
  other v1: -262.25,89.6
NetC218_2: C218.2 R311.2 U30.3 | length 8.3
  Top Layer w0.25: U30.3@-245.456,96.952 -244.127,96.952 -244.125,96.95 -243.9,96.95 -243.6,97.25 C218.2@-242.7,97.25 ; C218.2@-242.7,97.169 C218.2@-242.7,97.25 ; C218.2@-242.625,97.225 -242.65,97.25 C218.2@-242.7,97.25 ; R311.2@-239.025,97.325 -239.11,97.41 -239.11,97.91 -239.525,98.325 -242.375,98.325 -242.7,98 C218.2@-242.7,97.25
NetC219_2: C219.2 R314.2 U30.5 | length 8.9
  Top Layer w0.25: U30.5@-245.456,99.492 -243.917,99.492 -243.625,99.2 C219.2@-242.8,99.2 ; C219.2@-242.7,99.234 -242.825,99.359 -242.825,100 -241.825,101 -239.975,101 -239.2,100.225 -239.2,99.325 R314.2@-239.15,99.275
NetC221_1: C221.1 L25.2 R287.1 U30.18 | length 22.4
  Top Layer w0.25: v1@-264.8,89.65 -264.775,89.625 L25.2@-264.775,88.275 ; v1(-264.65,98.45) -257.7,98.45 -257.5,98.25 -257.5,97.533 R287.1@-257.61,97.423 -257.326,97.139 -256.889,97.139 -256.702,96.952 U30.18@-255.156,96.952 ; C221.1@-264.619,97.427 v1@-264.619,98.419
  Bottom Layer w0.25: v1@-264.8,89.8 -264.819,89.819 -264.819,90.219 -265.5,90.9 -265.5,94.352 -265.529,94.381 -265.529,94.819 -264.65,95.698 v1(-264.65,98.45)
  other v1: -264.825,89.7
NetC222_1: C222.1 L17.2 U31.1 | length 4.8
  Top Layer w0.25: U31.1@-244.92,55.169 -240.292,55.169 L17.2@-240.156,55.033
NetC229_1: C229.1 J7.2 Q2.2 U17.8 | length 10.8
  Top Layer w0.5: Q2.2@-66.468,19.583 -66.268,19.583 -66.026,19.341 Q2.2@-65.276,18.591 ; Q2.2@-66.453,18.05 -66.453,17.531 -66.16,17.238 -65.833,17.238 Q2.2@-65.706,17.303 ; Q2.2@-65.684,17.325 -65.171,16.976 Q2.2@-65.161,16.969 ; v1(-65.117,18.75) -65.117,18.432 -63.618,16.933 -63.311,16.933 -63.018,16.641 -63.018,15.203 -63.018,15.145 -62.418,14.007 cw(c-63.996,12.699) -62.303,13.854 -62.125,13.676 U17.8@-61.36,13.676
  other v1: -68.868,17.253 -68.118,17.253 -67.368,17.253 -66.618,17.253 -65.868,17.253 -65.118,17.253 -68.867,18 -68.117,18 -67.367,18 -66.617,18 -65.867,18 -65.117,18 -68.867,18.75 -68.117,18.75 -67.367,18.75 -66.617,18.75 -65.867,18.75 -68.867,19.5 -68.117,19.5 -67.367,19.5 -66.617,19.5 -65.867,19.5 -65.117,19.5 -68.867,20.25 -68.117,20.25 -67.367,20.25 -66.617,20.25 -65.867,20.25 -65.117,20.25 -68.867,21 -68.117,21 -67.367,21 -66.617,21 -65.867,21 -65.117,21
NetC230_2: C230.2 FB14.2 U20.8 | length 4.7
  Top Layer w0.25: FB14.2@-236.023,115.733 -235.033,115.733 -234.718,115.418 -233.828,115.418 C230.2@-233.778,115.468 -233.771,115.475 U20.8@-231.455,115.475
NetC233_1: C233.1 C236.2 C237.2 R288.1 R289.2 | length 8.3
  Top Layer w0.25: C233.1@-262.978,56.566 -262.978,58.222 C237.2@-262.9,58.3 ; C237.2@-262.9,58.4 C236.2@-260.946,58.4 ; C236.2@-260.946,58.382 -260.195,58.382 -259.327,57.514 -259.327,57.002 R288.1@-259.05,56.725 ; R289.2@-258.99,58.598 -258.99,57.165 R288.1@-258.8,56.975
